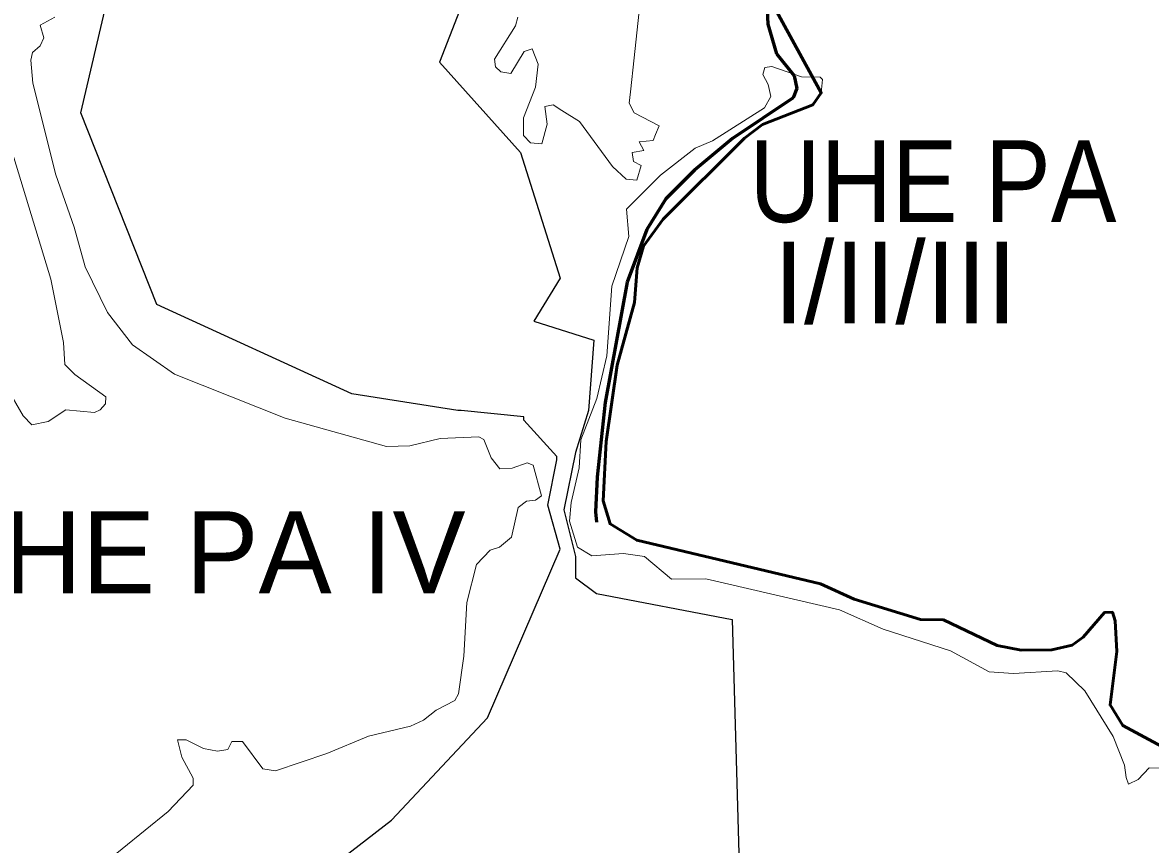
# Model space of a CAD drawing. Extents: x -1643653 to 4543381, y 1624270 to 13878484.
# Drawn here: x 583806 to 590692, y 8956904 to 8961924 of the extents above; entities that cross this region are included whole.
import ezdxf
from ezdxf.enums import TextEntityAlignment as Align

# ---------------------------------------------------------------- set-up
doc = ezdxf.new("R2010")
doc.units = 0
doc.header["$LTSCALE"] = 200
doc.linetypes.add('LONG_DASH_SHORT_DASH', pattern=[9.9, 6, -1.2, 1.5, -1.2])
for name, color, linetype, lineweight in [('1', 7, 'Continuous', 13), ('21', 7, 'Continuous', 25), ('25', 7, 'Continuous', 13), ('27', 7, 'Continuous', 53), ('28', 7, 'Continuous', 53), ('7', 7, 'LONG_DASH_SHORT_DASH', 60)]:
    doc.layers.add(name, color=color, linetype=linetype, lineweight=lineweight)
doc.layers.add('42', color=7, linetype='Continuous')

msp = doc.modelspace()

# ---------------------------------------------------------------- linework, layer by layer
at = {"layer": '1', "lineweight": 25}
msp.add_spline([(814781, 9009175.5), (814787.2, 9009173.4), (814796.9, 9009173.4), (814799.4, 9009172.4), (814805.1, 9009174.5), (814805.6, 9009176.5), (814811.7, 9009179.5), (814811.7, 9009179.5), (814801.5, 9009181), (814790.7, 9009181.5), (814784.1, 9009183.1), (814777.4, 9009185.1), (814778.4, 9009175.5)], degree=3, dxfattribs=at)
at = {"layer": '21'}
for points in [[(586765.6, 8962744.6), (586351.3, 8961682.2), (586846.3, 8961129.9), (587088.5, 8960362.9), (586927, 8960100.5)], [(586058.4, 8957052.4), (586644.6, 8957678.4), (587088.5, 8958707.8), (587013.2, 8958975.6), (587068.3, 8959252.8), (587068.3, 8959273), (586866.5, 8959495), (586866.5, 8959515.2), (586483.1, 8959555.5), (586463, 8959555.5), (585817.3, 8959656.5), (584626.8, 8960201.4), (584162.8, 8961372.1), (584384.7, 8962320.7)], [(586927, 8960100.5), (587293.7, 8959984.2), (587261.8, 8959553.8), (587182.2, 8959298.7), (587110, 8958948.6), (587182.2, 8958662.7), (587182.2, 8958533.5), (587309.6, 8958437.9), (588138.3, 8958278.5)], [(588138.3, 8958278.5), (588184.9, 8956636.2), (588170.1, 8956606.6), (588147.9, 8956599.2), (587104, 8956080.8), (587074.4, 8955769.7), (587148.4, 8955229.1)], [(587148.4, 8955229.1), (587155.8, 8955021.8), (587155.8, 8954992.1), (587163.2, 8954829.2), (587163.2, 8954644.1), (587163.2, 8954621.8), (587133.6, 8954540.4), (587037.4, 8954510.8), (584720.1, 8955044), (584653.5, 8955073.6), (584631.3, 8955081), (584601.7, 8955095.8), (584446.2, 8955169.9), (584416.6, 8955199.5), (584461, 8955695.7), (585223.6, 8956406.6), (586058.4, 8957052.4)]]:
    msp.add_lwpolyline(points, dxfattribs=at)
at = {"layer": '25'}
for points in [[(587781.7, 8962215.1), (587781.7, 8962215.1), (587718.2, 8962140.9), (587735, 8962113.3), (587792.4, 8962083.3), (587794.6, 8962050), (587745.5, 8962032.4), (587597.2, 8962100.2), (587563.1, 8962089.5), (587569.5, 8961975.7), (587540.2, 8961707.3), (587517.7, 8961501.6)], [(587781.7, 8962215.1), (587781.7, 8962215.1), (587718.2, 8962140.9), (587735, 8962113.3), (587792.4, 8962083.3), (587794.6, 8962050), (587745.5, 8962032.4), (587597.2, 8962100.2), (587563.1, 8962089.5), (587569.5, 8961975.7), (587540.2, 8961707.3), (587517.7, 8961501.6)], [(584002.7, 8961956), (583913.8, 8961907.2), (583936.8, 8961830.6), (583913.5, 8961781.7), (583866.6, 8961740.8), (583856.2, 8961694.6), (583869, 8961554.4), (584009.2, 8960993.4), (584121.2, 8960674.7), (584187.7, 8960432.6), (584325.6, 8960152.6), (584476.5, 8959954.9), (584733.5, 8959776.4), (585408.8, 8959506.7), (586028.5, 8959334.8), (586169.5, 8959338.8), (586356.5, 8959383.4), (586592.2, 8959394), (586621.9, 8959377), (586666.5, 8959264.6), (586719.8, 8959198.7), (586794.3, 8959202.9), (586887.5, 8959234.6), (586924.3, 8959221.3), (586974.5, 8959033.2), (586938.3, 8959007.4), (586883.3, 8959001), (586832.3, 8958962.8), (586791.8, 8958780.2), (586717.8, 8958720.8), (586660.1, 8958701.3), (586577.3, 8958614.2), (586518, 8958381), (586500.9, 8958053.6), (586466.9, 8957824.2), (586445.4, 8957783.8), (586330.8, 8957724.2), (586254.3, 8957662.7), (586173.8, 8957626.7)], [(584002.7, 8961956), (583913.8, 8961907.2), (583936.8, 8961830.6), (583913.5, 8961781.7), (583866.6, 8961740.8), (583856.2, 8961694.6), (583869, 8961554.4), (584009.2, 8960993.4), (584121.2, 8960674.7), (584187.7, 8960432.6), (584325.6, 8960152.6), (584476.5, 8959954.9), (584733.5, 8959776.4), (585408.8, 8959506.7), (586028.5, 8959334.8), (586169.5, 8959338.8), (586356.5, 8959383.4), (586592.2, 8959394), (586621.9, 8959377), (586666.5, 8959264.6), (586719.8, 8959198.7), (586794.3, 8959202.9), (586887.5, 8959234.6), (586924.3, 8959221.3), (586974.5, 8959033.2), (586938.3, 8959007.4), (586883.3, 8959001), (586832.3, 8958962.8), (586791.8, 8958780.2), (586717.8, 8958720.8), (586660.1, 8958701.3), (586577.3, 8958614.2), (586518, 8958381), (586500.9, 8958053.6), (586466.9, 8957824.2), (586445.4, 8957783.8), (586330.8, 8957724.2), (586254.3, 8957662.7), (586173.8, 8957626.7)], [(587098.4, 8961386.8), (587045, 8961420.4), (586993.8, 8961411.8), (587008.6, 8961303.5), (586976.2, 8961182.7), (586906.7, 8961189.1), (586864.3, 8961233.5), (586864.2, 8961341.7), (586938.6, 8961529.2), (586953.1, 8961669.7), (586916.8, 8961762.6), (586868.3, 8961747.5), (586787.2, 8961611.7), (586725.9, 8961622.5), (586694.3, 8961654.3), (586687.9, 8961700.7), (586815.2, 8961902.8), (586830.2, 8961956.5)], [(587098.4, 8961386.8), (587045, 8961420.4), (586993.8, 8961411.8), (587008.6, 8961303.5), (586976.2, 8961182.7), (586906.7, 8961189.1), (586864.3, 8961233.5), (586864.2, 8961341.7), (586938.6, 8961529.2), (586953.1, 8961669.7), (586916.8, 8961762.6), (586868.3, 8961747.5), (586787.2, 8961611.7), (586725.9, 8961622.5), (586694.3, 8961654.3), (586687.9, 8961700.7), (586815.2, 8961902.8), (586830.2, 8961956.5)], [(587368.2, 8959365.5), (587437, 8959830.7), (587541.6, 8960215), (587558.8, 8960425), (587596.7, 8960558.6), (587717.4, 8960723.2), (588213.5, 8961217.2), (588323.7, 8961300.9), (588630.6, 8961421.7), (588681.9, 8961493.8), (588689.2, 8961575.7), (588675.2, 8961590.7), (588561, 8961592.8), (588381.1, 8961656.2), (588338.6, 8961648.6), (588325.4, 8961606.6), (588359, 8961544.8), (588373.9, 8961471.3), (588335.7, 8961403.9), (588018, 8961201.6), (587911.6, 8961156.7), (587701, 8960992.4), (587493.3, 8960783.2), (587506.9, 8960616.2), (587403.7, 8960314.5), (587373.8, 8959887.7), (587311.1, 8959628.3), (587213.9, 8959375.4), (587204.9, 8959204), (587155.6, 8958993.5), (587145.5, 8958878.4), (587193.6, 8958719.2), (587281.8, 8958666.6), (587474.7, 8958681.2), (587603.9, 8958663), (587767.8, 8958525.1), (587976.7, 8958527.1), (588793.4, 8958337.9), (589059.2, 8958220.1), (589471.1, 8958087), (589708, 8957957.9), (589856.5, 8957947.6), (590127.1, 8957964.8), (590176.9, 8957951.8), (590291.3, 8957841.5), (590464.7, 8957564.3), (590533, 8957388.3), (590544.4, 8957313.3), (590557.7, 8957273.4), (590617.6, 8957300), (590684.2, 8957372.3), (590781.5, 8957369.6)], [(587517.7, 8961501.6), (587510, 8961431.2), (587539.9, 8961371.6), (587692.7, 8961292.6), (587670.8, 8961239.2)], [(587517.7, 8961501.6), (587510, 8961431.2), (587539.9, 8961371.6), (587692.7, 8961292.6), (587670.8, 8961239.2)], [(587670.8, 8961239.2), (587656.4, 8961204.1), (587570.6, 8961194.6), (587599.2, 8961141.8), (587527.1, 8961129.4), (587535.4, 8961074.6), (587582.5, 8961050.1), (587556.1, 8960961.2), (587491.1, 8960968.1), (587408.1, 8961044.4), (587205.3, 8961319.5), (587098.4, 8961386.8)], [(587670.8, 8961239.2), (587656.4, 8961204.1), (587570.6, 8961194.6), (587599.2, 8961141.8), (587527.1, 8961129.4), (587535.4, 8961074.6), (587582.5, 8961050.1), (587556.1, 8960961.2), (587491.1, 8960968.1), (587408.1, 8961044.4), (587205.3, 8961319.5), (587098.4, 8961386.8)], [(583684, 8959740.2), (583809.5, 8959521.5), (583862.6, 8959466.3), (583962.4, 8959487.6), (584070.6, 8959557.6), (584244.7, 8959542.8), (584281, 8959557.7), (584312.8, 8959595.8), (584315, 8959638.2), (584126, 8959774.3), (584064.3, 8959836.4), (584055.9, 8959969.5), (583979.3, 8960356.6), (583690.5, 8961308.2)], [(583684, 8959740.2), (583809.5, 8959521.5), (583862.6, 8959466.3), (583962.4, 8959487.6), (584070.6, 8959557.6), (584244.7, 8959542.8), (584281, 8959557.7), (584312.8, 8959595.8), (584315, 8959638.2), (584126, 8959774.3), (584064.3, 8959836.4), (584055.9, 8959969.5), (583979.3, 8960356.6), (583690.5, 8961308.2)], [(591321.1, 8957200.7), (590522.6, 8957630), (590445.4, 8957756.5), (590486.6, 8958082.5), (590475.5, 8958269.4), (590460, 8958322.7), (590411.3, 8958320.8), (590281.4, 8958169.9), (590213.4, 8958120.7), (590089.5, 8958093.2), (589901.7, 8958091.4), (589756.1, 8958120.1), (589428.5, 8958275.3), (589288.6, 8958277.6), (588883.2, 8958402.7), (588677.6, 8958496.7), (587555.9, 8958762.2), (587392.7, 8958862), (587351, 8959003.1), (587368.2, 8959365.5)], [(586173.8, 8957626.7), (585918.1, 8957564.8), (585664, 8957458.9), (585351.4, 8957354.8), (585272.9, 8957365.6), (585149.7, 8957533.1), (585084, 8957533), (585058.5, 8957484.5), (584997.2, 8957473.7), (584911.7, 8957490.8), (584806, 8957543.7), (584753, 8957543.8), (584778.1, 8957437.9), (584848.5, 8957309.3), (584847.7, 8957267), (584696, 8957104.7), (584274.9, 8956764.4)], [(586173.8, 8957626.7), (585918.1, 8957564.8), (585664, 8957458.9), (585351.4, 8957354.8), (585272.9, 8957365.6), (585149.7, 8957533.1), (585084, 8957533), (585058.5, 8957484.5), (584997.2, 8957473.7), (584911.7, 8957490.8), (584806, 8957543.7), (584753, 8957543.8), (584778.1, 8957437.9), (584848.5, 8957309.3), (584847.7, 8957267), (584696, 8957104.7), (584274.9, 8956764.4)]]:
    msp.add_lwpolyline(points, dxfattribs=at)
at = {"layer": '27'}
for points in [[(587368.2, 8959365.5), (587437, 8959830.7), (587541.6, 8960215), (587558.8, 8960425), (587596.7, 8960558.6), (587717.4, 8960723.2), (588213.5, 8961217.2), (588323.7, 8961300.9), (588630.6, 8961421.7), (588681.9, 8961493.8), (588387.5, 8962034), (588373.5, 8962049.1), (588381.1, 8962040.8)], [(591853.4, 8956904.4), (591520.9, 8957037.4), (591321.1, 8957200.7), (590522.6, 8957630), (590445.4, 8957756.5), (590486.6, 8958082.5), (590475.5, 8958269.4), (590460, 8958322.7), (590411.3, 8958320.8), (590281.4, 8958169.9), (590213.4, 8958120.7), (590089.5, 8958093.2), (589901.7, 8958091.4), (589756.1, 8958120.1), (589428.5, 8958275.3), (589288.6, 8958277.6), (588883.2, 8958402.7), (588677.6, 8958496.7), (587555.9, 8958762.2), (587392.7, 8958862), (587351, 8959003.1), (587368.2, 8959365.5)]]:
    msp.add_lwpolyline(points, dxfattribs=at)
at = {"layer": '28'}
for points in [[(588373.5, 8962049.1), (588387.5, 8962034), (588681.9, 8961493.8), (588630.6, 8961421.7), (588323.7, 8961300.9), (588213.5, 8961217.2), (587717.4, 8960723.2), (587596.7, 8960558.6), (587558.8, 8960425), (587541.6, 8960215), (587437, 8959830.7), (587368.2, 8959365.5)], [(588373.5, 8962049.1), (588387.5, 8962034), (588681.9, 8961493.8), (588630.6, 8961421.7), (588323.7, 8961300.9), (588213.5, 8961217.2), (587717.4, 8960723.2), (587596.7, 8960558.6), (587558.8, 8960425), (587541.6, 8960215), (587437, 8959830.7), (587368.2, 8959365.5)], [(587368.2, 8959365.5), (587351, 8959003.1), (587392.7, 8958862), (587555.9, 8958762.2), (588677.6, 8958496.7), (588883.2, 8958402.7), (589288.6, 8958277.6), (589428.5, 8958275.3), (589756.1, 8958120.1), (589901.7, 8958091.4), (590089.5, 8958093.2), (590213.4, 8958120.7), (590281.4, 8958169.9), (590411.3, 8958320.8), (590460, 8958322.7), (590475.5, 8958269.4), (590486.6, 8958082.5), (590445.4, 8957756.5), (590522.6, 8957630), (591321.1, 8957200.7)], [(587368.2, 8959365.5), (587351, 8959003.1), (587392.7, 8958862), (587555.9, 8958762.2), (588677.6, 8958496.7), (588883.2, 8958402.7), (589288.6, 8958277.6), (589428.5, 8958275.3), (589756.1, 8958120.1), (589901.7, 8958091.4), (590089.5, 8958093.2), (590213.4, 8958120.7), (590281.4, 8958169.9), (590411.3, 8958320.8), (590460, 8958322.7), (590475.5, 8958269.4), (590486.6, 8958082.5), (590445.4, 8957756.5), (590522.6, 8957630), (591321.1, 8957200.7)]]:
    msp.add_lwpolyline(points, dxfattribs=at)
at = {"layer": '7'}
msp.add_lwpolyline([(587540.9, 8964040.5), (587545.5, 8964019), (587739.9, 8963466), (587828.5, 8963155), (587886.8, 8963016.8), (588023, 8962809.1), (588321.3, 8962515.1), (588353.7, 8962454.8), (588379.7, 8962350), (588349.5, 8962039.7), (588356.1, 8961913.4), (588409.9, 8961732.7), (588515.9, 8961598.5), (588533, 8961520.2), (588511.4, 8961464.3), (588140, 8961216), (587908.2, 8961023.1), (587733.4, 8960846.2), (587616.5, 8960660), (587498.3, 8960337.4), (587362.2, 8959603), (587314, 8959147.2), (587303.2, 8958935.8), (587310.7, 8958873)], dxfattribs=at)

# ---------------------------------------------------------------- texts
at = {"layer": '42', "width": 0.9}
msp.add_text('UHE PA', height=500, dxfattribs=at).set_placement((589364.5, 8960705), align=Align.CENTER)
at = {"layer": '42'}
for s, p in [('I/II/III', (589134.4, 8960086.2)), ('UHE PA IV', (584857.3, 8958438.7))]:
    msp.add_text(s, height=500, dxfattribs=at).set_placement(p, align=Align.CENTER)

doc.saveas('drawing.dxf')
